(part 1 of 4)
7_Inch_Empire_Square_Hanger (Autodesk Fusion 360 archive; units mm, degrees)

design "7 Inch Empire Square Hanger" references "Speed Square_7IN_F360 v2"
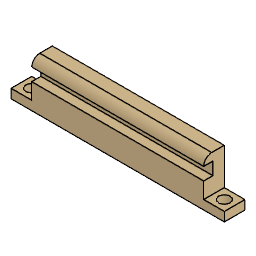
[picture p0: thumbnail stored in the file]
sketch "Square Hanger" plane through (0, 0, 0) normal (0, 0, 1) x axis (1, 0, 0)
  line L1 (75, 0) -> (0, 0)
  line L2 (75, 9) -> (75, 0)
  line L3 (0, 9) -> (75, 9)
  line L4 (0, 0) -> (0, 9)
  line L5 (-9, 0) -> (0, 0)
  line L6 (-9, 9) -> (-9, 0)
  line L7 (0, 9) -> (-9, 9)
  line L8 (0, 0) -> (0, 9)
  line L9 (84, 9) -> (75, 9)
  line L10 (84, 0) -> (84, 9)
  line L11 (75, 0) -> (84, 0)
  line L12 (75, 9) -> (75, 0)
  line L13 (79.5, 0) -> (79.5, 9)
  line L14 (84, 4.5) -> (75, 4.5)
  line L15 (0, 4.5) -> (-9, 4.5)
  line L16 (-4.5, 0) -> (-4.5, 9)
  circle C1 centre (79.5, 4.5) radius 2.5
  circle C2 centre (-4.5, 4.5) radius 2.5
  point P1 (0, 0)
  point P2 (0, 0)
  point P12 (79.5, 9)
  point P13 (79.5, 0)
  point P14 (75, 4.5)
  point P15 (84, 4.5)
  point P16 (-9, 4.5)
  point P17 (0, 4.5)
  point P18 (-4.5, 9)
  point P19 (-4.5, 0)
  point P20 (79.5, 4.5)
  point P21 (-4.5, 4.5)
  point P3 (75, 0)
  point P5 (0, 9)
  point P6 (-9, 0)
  point P8 (0, 9)
  point P4 (75, 9)
  point P9 (84, 9)
  point P11 (75, 0)
  horizontal L1
  vertical L2
  horizontal L3
  vertical L4
  coincident P1 P2
  horizontal L5
  vertical L6
  horizontal L7
  vertical L8
  horizontal L9
  vertical L10
  horizontal L11
  vertical L12
  midpoint L9 P12
  midpoint L11 P13
  midpoint L12 P14
  midpoint L10 P15
  midpoint L6 P16
  midpoint L8 P17
  midpoint L7 P18
  midpoint L5 P19
  midpoint L14 P20
  midpoint L15 P21
  dimension "d1" distance P2 P3 = 75
  dimension "d2" distance P2 P5 = 9
  dimension "d3" distance P2 P6 = 9 (= "d2")
  dimension "d4" distance P2 P8 = 9 (= "d2")
  dimension "d5" distance P4 P9 = 9 (= "d2")
  dimension "d6" distance P4 P11 = 9 (= "d2")
  dimension "d7" diameter C1 = 5
  dimension "d8" diameter C2 = 5
extrude "Extrude1" new body sketch "Square Hanger" profile of L1 L2 L3 L4 L8 L12 along normal blind 20 bodies "Square Hanger"
extrude "Extrude2" add sketch "Square Hanger" profile of L2 L4 L5 L6 L7 L8 L9 L10 L11 L12 C1 C2 along normal blind 4
sketch "Sketch2" plane through (0, 0, 0) normal (0, -1, 0) x axis (1, 0, 0)
  line L1 (84, 0) -> (-9, 0)
  line L2 (84, 4) -> (84, 0)
  line L3 (75, 4) -> (84, 4)
  line L4 (75, 20) -> (75, 4)
  line L5 (0, 20) -> (75, 20)
  line L6 (0, 4) -> (0, 20)
  line L7 (-9, 4) -> (0, 4)
  line L8 (-9, 0) -> (-9, 4)
  line L9 (0, 16.5) -> (75, 16.5)
  line L10 (0, 11) -> (0, 16.5)
  line L11 (75, 11) -> (0, 11)
  line L12 (75, 16.5) -> (75, 11)
  line L13 (75, 0) -> (0, 0)
  point P10 (75, 16.5)
  point P13 (75, 11)
  horizontal L9
  vertical L10
  horizontal L11
  vertical L12
  coincident L4 P10
  dimension "d13" distance P10 P13 = 5.5
  dimension "d14" distance L11 L13 = 11
extrude "Extrude3" cut sketch "Sketch2" profile of L4 L6 L9 L10 L11 L12 against normal blind 4
fillet "Fillet1" radius 3.5
component_insert "Component Insert"
named bodies: "Square Hanger"

design "Speed Square_7IN_F360 v2"
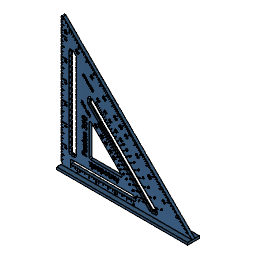
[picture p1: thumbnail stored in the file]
parameter "Etch_Diameter" = 0.635
parameter "Scale_Rule_Span" = 25.4
parameter "Scale_Triangle" = 177.8
parameter "Scale_Notch_Span" = 6.35
parameter "Square_Thickness" = 3.81
parameter "Square_Fense_Thickness" = 15.875
parameter "Scale_Rule_Depth" = 0.254
parameter "d473" = 3.175
sketch "MasterShape" plane through (0, 0, 0) normal (0, 1, 0) x axis (1, 0, 0)
  line L1 (177.8, 1.5875) -> (0, 1.5875)
  line L2 (0, -176.2125) -> (177.8, 1.5875)
  line L3 (0, 1.5875) -> (0, -176.2125)
  line L4 (177.8, 1.5875) -> (0, 1.5875)
  line L5 (177.8, 4.7625) -> (177.8, 1.5875)
  line L6 (0, 4.7625) -> (177.8, 4.7625)
  line L7 (0, 1.5875) -> (0, 4.7625)
  line L8 (19.05, -17.4625) -> (12.7, -17.4625)
  line L9 (19.05, -134.7119) -> (19.05, -17.4625)
  line L10 (12.7, -141.0619) -> (19.05, -134.7119)
  line L11 (12.7, -17.4625) -> (12.7, -141.0619)
  line L12 (104.0981, -4.7625) -> (12.7, -4.7625)
  line L13 (38.1, -70.7606) -> (104.0981, -4.7625)
  line L14 (38.1, -23.8125) -> (38.1, -70.7606)
  line L15 (38.1, -97.7013) -> (38.1, -88.7211)
  line L16 (131.0388, -4.7625) -> (38.1, -97.7013)
  line L17 (122.0586, -4.7625) -> (131.0388, -4.7625)
  line L18 (38.1, -88.7211) -> (122.0586, -4.7625)
  line L19 (38.1, -88.7211) -> (38.1, -70.7606)
  line L20 (85.0481, -23.8125) -> (38.1, -23.8125)
  line L21 (122.0586, -4.7625) -> (104.0981, -4.7625)
  line L22 (85.0481, -23.8125) -> (38.1, -70.7606)
  line L23 (12.7, -4.7625) -> (12.7, -17.4625)
  line L24 (12.7, -11.1125) -> (12.7, -4.7625)
  line L25 (97.7481, -11.1125) -> (12.7, -11.1125)
  line L26 (104.0981, -4.7625) -> (97.7481, -11.1125)
  arc A1 centre (0, 0) radius 1.5875 clockwise from (0, 1.5875) to (0, -1.5875)
  point P1 (0, 0)
  point P2 (0, 0)
  point P20 (0, -1.5875)
  point P21 (85.0481, -23.8125)
  point P22 (12.7, -11.1125)
  point P23 (97.7481, -11.1125)
  point P5 (0, -176.2125)
  point P3 (0, 1.5875)
  point P7 (0, 4.7625)
  point P12 (12.7, -4.7625)
  coincident P1 P2
  tangent L1 A1
  horizontal L1
  perpendicular L1 L3
  horizontal L4
  vertical L5
  horizontal L6
  vertical L7
  vertical L9
  vertical L11
  parallel L2 L10
  horizontal L12
  parallel L2 L13
  parallel L9 L15
  parallel L2 L16
  parallel L14 L19
  horizontal L17
  parallel L16 L18
  coincident L3 P20
  coincident L13 P21
  perpendicular L14 L20
  collinear L12 L17
  horizontal L8
  vertical L23
  coincident L23 P22
  perpendicular L12 L24
  coincident L13 P23
  perpendicular L23 L25
  dimension "d1" diameter A1 = 3.175
  dimension "d2" distance L1 P5 = 177.8 (= "Scale_Triangle")
  dimension "d3" angle L1 L2 = 45
  dimension "d4" distance P3 P7 = 3.175
  dimension "d5" distance L3 L11 = 12.7
  dimension "d6" distance L2 L10 = 15.875
  dimension "d7" distance L9 L11 = 6.35
  dimension "d8" distance L9 L14 = 19.05
  dimension "d12" distance L2 L13 = 47.625
  dimension "d13" distance L1 L17 = 6.35
  dimension "d15" distance L2 L18 = 34.925
  dimension "d16" distance L16 L18 = 6.35
  dimension "d72" distance L1 L8 = 19.05
  dimension "d73" distance L1 L20 = 25.4
  dimension "d74" distance P12 P22 = 6.35
  dimension "d564" distance P7 = 0.635
sketch "Inch_Scale" plane through (0, 0, 0) normal (0, 1, 0) x axis (1, 0, 0)
  line L1 (0, 1.5875) -> (0, -176.2125)
  line L2 (177.8, 1.5875) -> (0, 1.5875)
  line L3 (0, -176.2125) -> (177.8, 1.5875)
  line L4 (12.7, -17.4625) -> (12.7, -141.0619)
  line L5 (19.05, -134.7119) -> (19.05, -17.4625)
  line L6 (19.05, -17.4625) -> (12.7, -17.4625)
  line L7 (12.7, -141.0619) -> (19.05, -134.7119)
  line L8 (131.0388, -4.7625) -> (38.1, -97.7013)
  line L9 (38.1, -97.7013) -> (38.1, -88.7211)
  line L10 (38.1, -88.7211) -> (122.0586, -4.7625)
  line L11 (122.0586, -4.7625) -> (131.0388, -4.7625)
  line L12 (104.0981, -4.7625) -> (12.7, -4.7625)
  line L13 (38.1, -23.8125) -> (38.1, -70.7606)
  line L14 (38.1, -70.7606) -> (104.0981, -4.7625)
  line L15 (7.62, -24.13) -> (0, -24.13)
  line L16 (0, -20.32) -> (1.27, -20.32)
  line L17 (0, -23.495) -> (7.62, -23.495)
  line L18 (0, -17.145) -> (2.54, -17.145)
  line L19 (0, -17.4625) -> (2.54, -17.4625)
  line L20 (0, -1.27) -> (1.27, -1.27)
  line L21 (2.54, -5.08) -> (0, -5.08)
  line L22 (2.54, -17.78) -> (0, -17.78)
  line L23 (0, -1.5875) -> (1.27, -1.5875)
  line L24 (0, -23.8125) -> (7.62, -23.8125)
  line L25 (0, -11.1125) -> (3.81, -11.1125)
  line L26 (1.27, -20.955) -> (0, -20.955)
  line L27 (3.81, -11.43) -> (0, -11.43)
  line L28 (0, -14.2875) -> (1.27, -14.2875)
  line L29 (0, -10.795) -> (3.81, -10.795)
  line L30 (0, -4.445) -> (2.54, -4.445)
  line L31 (0, -4.7625) -> (2.54, -4.7625)
  line L32 (1.27, -8.255) -> (0, -8.255)
  line L33 (0, -13.97) -> (1.27, -13.97)
  line L34 (0, -7.9375) -> (1.27, -7.9375)
  line L35 (0, -7.62) -> (1.27, -7.62)
  line L36 (1.27, -1.905) -> (0, -1.905)
  line L37 (1.27, -14.605) -> (0, -14.605)
  line L38 (0, -20.6375) -> (1.27, -20.6375)
  line L39 (15.5575, -4.7625) -> (15.5575, -3.4925)
  line L40 (16.1925, -3.4925) -> (16.1925, -4.7625)
  line L41 (15.875, -4.7625) -> (15.875, -3.4925)
  line L42 (12.3825, -4.7625) -> (12.3825, -0.9525)
  line L43 (13.0175, -0.9525) -> (13.0175, -4.7625)
  line L44 (12.7, -4.7625) -> (12.7, -0.9525)
  line L45 (18.7325, -4.7625) -> (18.7325, -2.2225)
  line L46 (19.3675, -2.2225) -> (19.3675, -4.7625)
  line L47 (19.05, -4.7625) -> (19.05, -2.2225)
  line L48 (21.9075, -4.7625) -> (21.9075, -3.4925)
  line L49 (22.5425, -3.4925) -> (22.5425, -4.7625)
  line L50 (22.225, -4.7625) -> (22.225, -3.4925)
  line L51 (12.7, -23.8125) -> (7.62, -23.8125)
  line L52 (12.954, -25.059) -> (10.795, -23.8125)
  line L53 (12.954, -22.566) -> (12.954, -25.059)
  line L54 (10.795, -23.8125) -> (12.954, -22.566)
  line L55 (12.954, -23.8125) -> (12.7, -23.8125)
  line L56 (19.05, -20.6375) -> (1.27, -20.6375)
  line L57 (20.955, -20.6375) -> (19.05, -20.6375)
  line L58 (18.796, -21.884) -> (20.955, -20.6375)
  line L59 (18.796, -19.391) -> (18.796, -21.884)
  line L60 (20.955, -20.6375) -> (18.796, -19.391)
  arc A1 centre (1.27, -1.5875) radius 0.3175 clockwise from (1.27, -1.27) to (1.27, -1.905)
  arc A2 centre (1.27, -7.9375) radius 0.3175 clockwise from (1.27, -7.62) to (1.27, -8.255)
  arc A3 centre (2.54, -4.7625) radius 0.3175 clockwise from (2.54, -4.445) to (2.54, -5.08)
  arc A4 centre (1.27, -20.6375) radius 0.3175 clockwise from (1.27, -20.32) to (1.27, -20.955)
  arc A5 centre (0, -1.5875) radius 0.3175 clockwise from (0, -1.905) to (0, -1.27)
  arc A6 centre (0, -20.6375) radius 0.3175 clockwise from (0, -20.955) to (0, -20.32)
  arc A7 centre (0, -11.1125) radius 0.3175 clockwise from (0, -11.43) to (0, -10.795)
  arc A8 centre (0, -17.4625) radius 0.3175 clockwise from (0, -17.78) to (0, -17.145)
  arc A9 centre (0, -23.8125) radius 0.3175 clockwise from (0, -24.13) to (0, -23.495)
  arc A10 centre (0, -7.9375) radius 0.3175 clockwise from (0, -8.255) to (0, -7.62)
  arc A11 centre (2.54, -17.4625) radius 0.3175 clockwise from (2.54, -17.145) to (2.54, -17.78)
  arc A12 centre (7.62, -23.8125) radius 0.3175 clockwise from (7.62, -23.495) to (7.62, -24.13)
  arc A13 centre (1.27, -14.2875) radius 0.3175 clockwise from (1.27, -13.97) to (1.27, -14.605)
  arc A14 centre (0, -4.7625) radius 0.3175 clockwise from (0, -5.08) to (0, -4.445)
  arc A15 centre (0, -14.2875) radius 0.3175 clockwise from (0, -14.605) to (0, -13.97)
  arc A16 centre (3.81, -11.1125) radius 0.3175 clockwise from (3.81, -10.795) to (3.81, -11.43)
  arc A17 centre (15.875, -4.7625) radius 0.3175 clockwise from (16.1925, -4.7625) to (15.5575, -4.7625)
  arc A18 centre (15.875, -3.4925) radius 0.3175 clockwise from (15.5575, -3.4925) to (16.1925, -3.4925)
  arc A19 centre (12.7, -4.7625) radius 0.3175 clockwise from (13.0175, -4.7625) to (12.3825, -4.7625)
  arc A20 centre (12.7, -0.9525) radius 0.3175 clockwise from (12.3825, -0.9525) to (13.0175, -0.9525)
  arc A21 centre (19.05, -4.7625) radius 0.3175 clockwise from (19.3675, -4.7625) to (18.7325, -4.7625)
  arc A22 centre (19.05, -2.2225) radius 0.3175 clockwise from (18.7325, -2.2225) to (19.3675, -2.2225)
  arc A23 centre (22.225, -4.7625) radius 0.3175 clockwise from (22.5425, -4.7625) to (21.9075, -4.7625)
  arc A24 centre (22.225, -3.4925) radius 0.3175 clockwise from (21.9075, -3.4925) to (22.5425, -3.4925)
  point P1 (0, 0)
  point P35 (0, 0)
  point P73 (0, -1.5875)
  point P74 (0, -1.5875)
  point P32 (0, -4.7625)
  point P42 (0, -7.9375)
  point P44 (0, -11.1125)
  point P52 (0, -14.2875)
  point P79 (0, -17.4625)
  point P66 (0, -20.6375)
  point P46 (0, -23.8125)
  point P85 (15.875, -4.7625)
  point P24 (12.7, -4.7625)
  point P92 (12.7, -4.7625)
  point P98 (19.05, -4.7625)
  point P103 (22.225, -4.7625)
  point P54 (7.62, -23.8125)
  point P105 (7.62, -23.8125)
  point P106 (12.7, -23.8125)
  point P107 (10.795, -23.8125)
  point P110 (12.954, -23.8125)
  point P65 (1.27, -20.6375)
  point P111 (1.27, -20.6375)
  point P112 (19.05, -20.6375)
  point P116 (18.796, -20.6375)
  point P41 (3.81, -11.1125)
  point P31 (2.54, -4.7625)
  point P75 (2.54, -17.4625)
  point P40 (1.27, -7.9375)
  point P51 (1.27, -14.2875)
  point P64 (1.27, -1.5875)
  point P84 (15.875, -3.4925)
  point P86 (0, 0)
  point P91 (12.7, -0.9525)
  point P97 (19.05, -2.2225)
  point P100 (22.225, -3.4925)
  point P113 (20.955, -20.6375)
  tangent L17 A9
  tangent L15 A9
  parallel L15 L17
  tangent L15 A12
  tangent L17 A12
  tangent A7 L29
  tangent A7 L27
  parallel L27 L29
  tangent L27 A16
  tangent L29 A16
  tangent A14 L30
  tangent L21 A14
  parallel L21 L30
  tangent A3 L21
  tangent A3 L30
  tangent L18 A8
  tangent A8 L22
  parallel L18 L22
  tangent L22 A11
  tangent L18 A11
  horizontal L19
  tangent A10 L35
  tangent A10 L32
  parallel L32 L35
  tangent A2 L32
  tangent A2 L35
  tangent A15 L33
  tangent A15 L37
  parallel L33 L37
  tangent A13 L37
  tangent A13 L33
  tangent L16 A6
  tangent A6 L26
  parallel L16 L26
  tangent A4 L26
  tangent L16 A4
  tangent A5 L20
  tangent A5 L36
  parallel L20 L36
  tangent A1 L36
  tangent A1 L20
  coincident P1 P35
  coincident P73 P74
  coincident L1 P74
  coincident L1 P32
  coincident L1 P42
  coincident L1 P44
  coincident L1 P52
  coincident L1 P79
  coincident L1 P66
  coincident L1 P46
  tangent L39 A17
  tangent A17 L40
  parallel L39 L40
  tangent L40 A18
  tangent L39 A18
  coincident L12 P85
  perpendicular L12 L41
  tangent L42 A19
  tangent A19 L43
  parallel L42 L43
  tangent L43 A20
  tangent L42 A20
  coincident P24 P92
  perpendicular L12 L44
  tangent L45 A21
  tangent A21 L46
  parallel L45 L46
  tangent L46 A22
  tangent L45 A22
  coincident L12 P98
  perpendicular L12 L47
  tangent L48 A23
  tangent A23 L49
  parallel L48 L49
  tangent L49 A24
  tangent L48 A24
  coincident L12 P103
  vertical L50
  coincident P54 P105
  coincident L4 P106
  horizontal L51
  coincident L51 P107
  perpendicular L51 L53
  midpoint L53 P110
  horizontal L55
  coincident P65 P111
  coincident L5 P112
  horizontal L56
  perpendicular L5 L57
  perpendicular L56 L59
  midpoint L59 P116
  coincident L56 P116
  dimension "d46" diameter A9 = 0.635
  dimension "d47" distance P46 P54 = 7.62
  dimension "d48" diameter A7 = 0.635 (= "d60")
  dimension "d49" distance P41 P44 = 3.81
  dimension "d50" diameter A14 = 0.635 (= "d60")
  dimension "d51" distance P31 P32 = 2.54
  dimension "d52" diameter A8 = 0.635
  dimension "d53" distance P75 P79 = 2.54
  dimension "d54" diameter A10 = 0.635 (= "d60")
  dimension "d55" distance P40 P42 = 1.27
  dimension "d56" diameter A15 = 0.635
  dimension "d57" distance P51 P52 = 1.27
  dimension "d58" diameter A6 = 0.635
  dimension "d59" distance P65 P66 = 1.27
  dimension "d60" diameter A5 = 0.635
  dimension "d61" distance P64 P73 = 1.27
  dimension "d63" distance L2 L23 = 3.175 (= "0.125 in * ( Scale )")
  dimension "d64" distance L2 L31 = 6.35 (= "0.25 in * ( Scale )")
  dimension "d65" distance L2 L34 = 9.525 (= "0.375 in * ( Scale )")
  dimension "d66" distance L2 L25 = 12.7 (= "0.50 in * ( Scale )")
  dimension "d67" distance L2 L28 = 15.875 (= "0.625 in * ( Scale )")
  dimension "d68" distance L2 L19 = 19.05 (= "0.75 in * ( Scale )")
  dimension "d69" distance L2 L38 = 22.225 (= "0.875 in * ( Scale )")
  dimension "d70" distance L2 L24 = 25.4 (= "1.00 in * ( Scale )")
  dimension "d80" diameter A17 = 0.635 (= "d60")
  dimension "d81" distance P84 P85 = 1.27
  dimension "d82" distance L41 P86 = 15.875
  dimension "d83" diameter A19 = 0.635
  dimension "d84" distance P91 P92 = 3.81
  dimension "d85" diameter A21 = 0.635
  dimension "d86" distance P97 P98 = 2.54
  dimension "d87" distance L1 L47 = 19.05
  dimension "d88" diameter A23 = 0.635 (= "d60")
  dimension "d89" distance P100 P103 = 1.27
  dimension "d90" distance P86 L50 = 22.225
  dimension "d95" distance L4 L53 = 0.254
  dimension "d96" angle L52 L54 = 60
  dimension "d97" distance P106 P107 = 1.905
  dimension "d101" distance L5 L59 = 0.254 (= "d95")
  dimension "d102" distance P112 P113 = 1.905 (= "d97")
  dimension "d103" angle L58 L60 = 60 (= "d96")
sketch "Front_Scale_Text" plane through (0, 0, 0) normal (0, 1, 0) x axis (1, 0, 0)
  line L1 (7.9375, -20.6375) -> (4.7625, -20.6375)
  line L2 (7.9375, -19.05) -> (7.9375, -22.225)
  line L3 (7.9375, -46.0375) -> (4.7625, -46.0375)
  line L4 (7.9375, -44.3107) -> (7.9375, -47.7643)
  line L5 (7.9375, -69.85) -> (7.9375, -73.025)
  line L6 (7.9375, -71.4375) -> (4.7625, -71.4375)
  line L7 (7.9375, -122.2375) -> (4.7625, -122.2375)
  line L8 (7.9375, -96.8375) -> (4.7625, -96.8375)
  line L9 (7.9375, -120.65) -> (7.9375, -123.825)
  line L10 (7.9375, -95.25) -> (7.9375, -98.425)
  line L11 (7.9375, -147.6375) -> (0, -147.6375)
  line L12 (7.9375, -146.05) -> (7.9375, -149.225)
  line L13 (7.9375, -171.45) -> (7.9375, -174.625)
  line L14 (7.9375, -173.0375) -> (4.7625, -173.0375)
  line L15 (7.9375, -300.0375) -> (4.7625, -300.0375)
  line L16 (7.9375, -198.4375) -> (4.7625, -198.4375)
  line L17 (7.9375, -223.8375) -> (4.7625, -223.8375)
  line L18 (7.9375, -222.25) -> (7.9375, -225.425)
  line L19 (7.9375, -247.65) -> (7.9375, -250.825)
  line L20 (7.9375, -273.05) -> (7.9375, -276.225)
  line L21 (7.9375, -249.2375) -> (4.7625, -249.2375)
  line L22 (7.9375, -274.6375) -> (4.7625, -274.6375)
  line L23 (7.9375, -298.45) -> (7.9375, -301.625)
  line L24 (7.9375, -196.85) -> (7.9375, -200.025)
  line L25 (0, 1.5875) -> (0, -176.2125)
  line L26 (177.8, 1.5875) -> (0, 1.5875)
  line L27 (0, -176.2125) -> (177.8, 1.5875)
  line L28 (12.7, -17.4625) -> (12.7, -141.0619)
  line L29 (12.7, -141.0619) -> (19.05, -134.7119)
  line L30 (19.05, -134.7119) -> (19.05, -17.4625)
  line L31 (19.05, -17.4625) -> (12.7, -17.4625)
  line L32 (97.7481, -11.1125) -> (12.7, -11.1125)
  line L33 (12.7, -4.7625) -> (12.7, -17.4625)
  line L34 (104.0981, -4.7625) -> (12.7, -4.7625)
  line L35 (38.1, -70.7606) -> (104.0981, -4.7625)
  line L36 (85.0481, -23.8125) -> (38.1, -23.8125)
  line L37 (38.1, -23.8125) -> (38.1, -70.7606)
  line L38 (38.1, -88.7211) -> (122.0586, -4.7625)
  line L39 (131.0388, -4.7625) -> (38.1, -97.7013)
  line L40 (38.1, -97.7013) -> (38.1, -88.7211)
  line L41 (122.0586, -4.7625) -> (131.0388, -4.7625)
  line L42 (23.7727, 0.9525) -> (20.6773, 0.9525)
  line L43 (49.1727, 0.9525) -> (46.0773, 0.9525)
  line L44 (74.5727, 0.9525) -> (71.4773, 0.9525)
  line L45 (99.9727, 0.9525) -> (96.8773, 0.9525)
  line L46 (125.3727, 0.9525) -> (122.2773, 0.9525)
  line L47 (150.7727, 0.9525) -> (147.6773, 0.9525)
  line L48 (176.1727, 0.9525) -> (173.0773, 0.9525)
  line L49 (201.5727, 0.9525) -> (198.4773, 0.9525)
  line L50 (226.9727, 0.9525) -> (223.8773, 0.9525)
  line L51 (7.9375, -155.575) -> (7.9375, -158.75)
  line L52 (7.9375, -157.1625) -> (0, -157.1625)
  point P46 (7.9375, -20.6375)
  point P20 (7.9375, -46.0375)
  point P2 (7.9375, -71.4375)
  point P32 (7.9375, -96.8375)
  point P45 (7.9375, -122.2375)
  point P34 (7.9375, -147.6375)
  point P6 (7.9375, -173.0375)
  point P29 (7.9375, -198.4375)
  point P24 (7.9375, -223.8375)
  point P11 (7.9375, -249.2375)
  point P38 (7.9375, -274.6375)
  point P14 (7.9375, -300.0375)
  point P86 (22.225, 0.9525)
  point P89 (47.625, 0.9525)
  point P92 (73.025, 0.9525)
  point P95 (98.425, 0.9525)
  point P98 (123.825, 0.9525)
  point P101 (149.225, 0.9525)
  point P104 (174.625, 0.9525)
  point P107 (200.025, 0.9525)
  point P110 (225.425, 0.9525)
  point P35 (0, -147.6375)
  point P111 (7.9375, -157.1625)
  vertical L2
  midpoint P46 L2
  vertical L4
  midpoint P20 L4
  vertical L5
  midpoint P2 L5
  vertical L10
  midpoint P32 L10
  vertical L9
  midpoint P45 L9
  vertical L12
  midpoint P34 L12
  vertical L13
  midpoint P6 L13
  collinear L2 L4
  collinear L4 L5
  collinear L5 L10
  collinear L9 L10
  collinear L9 L12
  collinear L12 L13
  vertical L24
  midpoint P29 L24
  vertical L18
  midpoint P24 L18
  vertical L19
  midpoint P11 L19
  vertical L20
  midpoint P38 L20
  vertical L23
  midpoint P14 L23
  collinear L13 L24
  collinear L18 L24
  collinear L18 L20
  collinear L19 L23
  collinear L20 L23
  horizontal L42
  midpoint L42 P86
  horizontal L43
  midpoint P89 L43
  horizontal L44
  midpoint P92 L44
  horizontal L45
  midpoint P95 L45
  horizontal L46
  midpoint P98 L46
  horizontal L47
  midpoint P101 L47
  horizontal L48
  midpoint P104 L48
  horizontal L49
  midpoint P107 L49
  horizontal L50
  midpoint P110 L50
  collinear L42 L43
  collinear L43 L44
  collinear L44 L45
  collinear L45 L46
  collinear L46 L47
  collinear L47 L48
  collinear L48 L49
  collinear L49 L50
  coincident P35 L25
  vertical L51
  midpoint P111 L51
  dimension "d429" distance L3 L6 = 25.4 (= "Scale_Rule_Span")
  dimension "d430" distance L6 L8 = 25.4 (= "Scale_Rule_Span")
  dimension "d431" distance L7 L8 = 25.4 (= "Scale_Rule_Span")
  dimension "d432" distance L7 L11 = 25.4 (= "Scale_Rule_Span")
  dimension "d433" distance L11 L14 = 25.4 (= "Scale_Rule_Span")
  dimension "d444" distance L14 L16 = 25.4 (= "Scale_Rule_Span")
  dimension "d445" distance L16 L17 = 25.4 (= "Scale_Rule_Span")
  dimension "d446" distance L17 L21 = 25.4 (= "Scale_Rule_Span")
  dimension "d447" distance L21 L22 = 25.4 (= "Scale_Rule_Span")
  dimension "d448" distance L15 L22 = 25.4 (= "Scale_Rule_Span")
  dimension "d449" distance L1 L26 = 22.225
  dimension "d450" distance L1 L3 = 25.4 (= "Scale_Rule_Span")
  dimension "d451" distance L2 L25 = 7.9375
  dimension "d503" distance L25 P86 = 22.225
  dimension "d505" distance L26 L42 = 0.635
  dimension "d1049" distance L11 L52 = 9.525 (= "Scale_Rule_Span * 0.375")
  dimension "d403" Text1-Height = 3.175
  dimension "d404" Text2-Height = 3.175
  dimension "d405" Text3-Height = 3.175
  dimension "d406" Text4-Height = 3.175
  dimension "d407" Text5-Height = 3.175
  dimension "d408" Text6-Height = 3.175
  dimension "d409" Text7-Height = 3.175
  dimension "d410" Text8-Height = 3.175
  dimension "d411" Text9-Height = 3.175
  dimension "d412" Text10-Height = 3.175
  dimension "d413" Text11-Height = 3.175
  dimension "d414" Text12-Height = 3.175
  dimension "d504" Text13-Height = 3.175
  dimension "d506" Text14-Height = 3.175
  dimension "d507" Text15-Height = 3.175
  dimension "d508" Text16-Height = 3.175
  dimension "d509" Text17-Height = 3.175
  dimension "d510" Text18-Height = 3.175
  dimension "d511" Text19-Height = 3.175
  dimension "d512" Text20-Height = 3.175
  dimension "d513" Text21-Height = 3.175
  dimension "d1048" Text22-Height = 3.175
sketch "Back_Scale_Text" plane through (0, 0, 0) normal (0, 1, 0) x axis (1, 0, 0)
  line L1 (4.7625, -149.225) -> (4.7625, -146.05)
  line L2 (4.7625, -98.425) -> (4.7625, -95.25)
  line L3 (7.9375, -200.025) -> (4.7625, -200.025)
  line L4 (7.9375, -222.25) -> (7.9375, -225.425)
  line L5 (7.9375, -73.025) -> (4.7625, -73.025)
  line L6 (4.7625, -225.425) -> (4.7625, -222.25)
  line L7 (4.7625, -95.25) -> (7.9375, -95.25)
  line L8 (4.7625, -19.05) -> (7.9375, -19.05)
  line L9 (7.9375, -225.425) -> (4.7625, -225.425)
  line L10 (7.9375, -46.0375) -> (4.7625, -46.0375)
  line L11 (4.7625, -47.625) -> (4.7625, -44.45)
  line L12 (7.9375, -47.625) -> (4.7625, -47.625)
  line L13 (4.7625, -146.05) -> (7.9375, -146.05)
  line L14 (7.9375, -149.225) -> (4.7625, -149.225)
  line L15 (4.7625, -200.025) -> (4.7625, -196.85)
  line L16 (4.7625, -44.45) -> (7.9375, -44.45)
  line L17 (4.7625, -120.65) -> (7.9375, -120.65)
  line L18 (7.9375, -96.8375) -> (4.7625, -96.8375)
  line L19 (7.9375, -98.425) -> (4.7625, -98.425)
  line L20 (4.7625, -250.825) -> (4.7625, -247.65)
  line L21 (7.9375, -249.2375) -> (4.7625, -249.2375)
  line L22 (7.9375, -276.225) -> (4.7625, -276.225)
  line L23 (7.9375, -147.6375) -> (4.7625, -147.6375)
  line L24 (7.9375, -250.825) -> (4.7625, -250.825)
  line L25 (4.7625, -247.65) -> (7.9375, -247.65)
  line L26 (4.7625, -276.225) -> (4.7625, -273.05)
  line L27 (4.7625, -298.45) -> (7.9375, -298.45)
  line L28 (7.9375, -274.6375) -> (4.7625, -274.6375)
  line L29 (7.9375, -301.625) -> (4.7625, -301.625)
  line L30 (4.7625, -301.625) -> (4.7625, -298.45)
  line L31 (7.9375, -300.0375) -> (4.7625, -300.0375)
  line L32 (4.7625, -273.05) -> (7.9375, -273.05)
  line L33 (7.9375, -22.225) -> (4.7625, -22.225)
  line L34 (4.7625, -123.825) -> (4.7625, -120.65)
  line L35 (7.9375, -223.8375) -> (4.7625, -223.8375)
  line L36 (7.9375, -122.2375) -> (4.7625, -122.2375)
  line L37 (7.9375, -20.6375) -> (4.7625, -20.6375)
  line L38 (4.7625, -69.85) -> (7.9375, -69.85)
  line L39 (7.9375, -71.4375) -> (4.7625, -71.4375)
  line L40 (4.7625, -22.225) -> (4.7625, -19.05)
  line L41 (7.9375, -123.825) -> (4.7625, -123.825)
  line L42 (4.7625, -222.25) -> (7.9375, -222.25)
  line L43 (4.7625, -73.025) -> (4.7625, -69.85)
  line L44 (7.9375, -44.45) -> (7.9375, -47.625)
  line L45 (4.7625, -174.625) -> (4.7625, -171.45)
  line L46 (7.9375, -174.625) -> (4.7625, -174.625)
  line L47 (4.7625, -196.85) -> (7.9375, -196.85)
  line L48 (7.9375, -198.4375) -> (4.7625, -198.4375)
  line L49 (7.9375, -171.45) -> (7.9375, -174.625)
  line L50 (7.9375, -19.05) -> (7.9375, -22.225)
  line L51 (7.9375, -95.25) -> (7.9375, -98.425)
  line L52 (7.9375, -69.85) -> (7.9375, -73.025)
  line L53 (7.9375, -273.05) -> (7.9375, -276.225)
  line L54 (7.9375, -196.85) -> (7.9375, -200.025)
  line L55 (7.9375, -120.65) -> (7.9375, -123.825)
  line L56 (7.9375, -146.05) -> (7.9375, -149.225)
  line L57 (7.9375, -173.0375) -> (4.7625, -173.0375)
  line L58 (7.9375, -298.45) -> (7.9375, -301.625)
  line L59 (7.9375, -247.65) -> (7.9375, -250.825)
  line L60 (4.7625, -171.45) -> (7.9375, -171.45)
  line L61 (0, 1.5875) -> (0, -176.2125)
  line L62 (177.8, 1.5875) -> (0, 1.5875)
  line L63 (0, -176.2125) -> (177.8, 1.5875)
  line L64 (19.05, -134.7119) -> (19.05, -17.4625)
  line L65 (12.7, -141.0619) -> (19.05, -134.7119)
  line L66 (12.7, -17.4625) -> (12.7, -141.0619)
  line L67 (19.05, -17.4625) -> (12.7, -17.4625)
  line L68 (97.7481, -11.1125) -> (12.7, -11.1125)
  line L69 (104.0981, -4.7625) -> (12.7, -4.7625)
  line L70 (12.7, -4.7625) -> (12.7, -17.4625)
  line L71 (38.1, -70.7606) -> (104.0981, -4.7625)
  line L72 (85.0481, -23.8125) -> (38.1, -23.8125)
  line L73 (38.1, -23.8125) -> (38.1, -70.7606)
  line L74 (38.1, -88.7211) -> (122.0586, -4.7625)
  line L75 (38.1, -97.7013) -> (38.1, -88.7211)
  line L76 (131.0388, -4.7625) -> (38.1, -97.7013)
  line L77 (122.0586, -4.7625) -> (131.0388, -4.7625)
  line L78 (24.1061, 0.9525) -> (20.3439, 0.9525)
  line L79 (49.5061, 0.9525) -> (45.7439, 0.9525)
  line L80 (74.9061, 0.9525) -> (71.1439, 0.9525)
  line L81 (100.3061, 0.9525) -> (96.5439, 0.9525)
  line L82 (125.7061, 0.9525) -> (121.9439, 0.9525)
  line L83 (151.1061, 0.9525) -> (147.3439, 0.9525)
  line L84 (176.5061, 0.9525) -> (172.7439, 0.9525)
  line L85 (201.9061, 0.9525) -> (198.1439, 0.9525)
  line L86 (227.3061, 0.9525) -> (223.5439, 0.9525)
  line L87 (7.9375, -157.1625) -> (0, -157.1625)
  line L88 (7.9375, -155.575) -> (7.9375, -158.75)
  point P3 (4.7625, -20.6375)
  point P8 (7.9375, -20.6375)
  point P61 (4.7625, -46.0375)
  point P56 (7.9375, -46.0375)
  point P29 (4.7625, -71.4375)
  point P27 (7.9375, -71.4375)
  point P64 (4.7625, -96.8375)
  point P54 (7.9375, -96.8375)
  point P12 (4.7625, -122.2375)
  point P5 (7.9375, -122.2375)
  point P66 (4.7625, -147.6375)
  point P69 (7.9375, -147.6375)
  point P24 (4.7625, -173.0375)
  point P36 (7.9375, -173.0375)
  point P55 (4.7625, -198.4375)
  point P51 (7.9375, -198.4375)
  point P62 (4.7625, -223.8375)
  point P60 (7.9375, -223.8375)
  point P22 (4.7625, -249.2375)
  point P38 (7.9375, -249.2375)
  point P19 (4.7625, -274.6375)
  point P20 (7.9375, -274.6375)
  point P43 (4.7625, -300.0375)
  point P33 (7.9375, -300.0375)
  point P112 (22.225, 0.9525)
  point P113 (47.625, 0.9525)
  point P116 (73.025, 0.9525)
  point P119 (98.425, 0.9525)
  point P122 (123.825, 0.9525)
  point P125 (149.225, 0.9525)
  point P128 (174.625, 0.9525)
  point P131 (200.025, 0.9525)
  point P134 (225.425, 0.9525)
  point P139 (7.9375, -157.1625)
  point P7 (7.9375, -19.05)
  point P9 (4.7625, -19.05)
  point P4 (7.9375, -22.225)
  point P45 (7.9375, -44.45)
  point P58 (4.7625, -44.45)
  point P46 (7.9375, -47.625)
  point P26 (4.7625, -69.85)
  point P28 (7.9375, -69.85)
  point P35 (7.9375, -73.025)
  point P49 (4.7625, -95.25)
  point P53 (7.9375, -95.25)
  point P63 (7.9375, -98.425)
  point P16 (4.7625, -120.65)
  point P17 (7.9375, -120.65)
  point P11 (7.9375, -123.825)
  point P10 (7.9375, -146.05)
  point P65 (4.7625, -146.05)
  point P70 (7.9375, -149.225)
  point P31 (7.9375, -171.45)
  point P34 (4.7625, -171.45)
  point P37 (7.9375, -174.625)
  point P57 (7.9375, -196.85)
  point P71 (4.7625, -196.85)
  point P50 (7.9375, -200.025)
  point P52 (7.9375, -222.25)
  point P59 (4.7625, -222.25)
  point P72 (7.9375, -225.425)
  point P23 (7.9375, -247.65)
  point P32 (4.7625, -247.65)
  point P39 (7.9375, -250.825)
  point P14 (4.7625, -273.05)
  point P15 (7.9375, -273.05)
  point P13 (7.9375, -276.225)
  point P25 (7.9375, -298.45)
  point P42 (4.7625, -298.45)
  point P41 (7.9375, -301.625)
  horizontal L33
  vertical L50
  horizontal L8
  vertical L40
  midpoint P3 L40
  midpoint P8 L50
  horizontal L12
  vertical L44
  horizontal L16
  vertical L11
  midpoint P61 L11
  midpoint P56 L44
  horizontal L5
  vertical L52
  horizontal L38
  vertical L43
  midpoint P29 L43
  midpoint P27 L52
  horizontal L19
  vertical L51
  horizontal L7
  vertical L2
  midpoint P64 L2
  midpoint P54 L51
  horizontal L41
  vertical L55
  horizontal L17
  vertical L34
  midpoint P12 L34
  midpoint P5 L55
  horizontal L14
  vertical L56
  horizontal L13
  vertical L1
  midpoint P66 L1
  midpoint P69 L56
  horizontal L46
  vertical L49
  horizontal L60
  vertical L45
  midpoint P24 L45
  midpoint P36 L49
  collinear L44 L50
  collinear L44 L52
  collinear L51 L52
  collinear L51 L55
  collinear L55 L56
  collinear L49 L56
  horizontal L3
  vertical L54
  horizontal L47
  vertical L15
  midpoint P55 L15
  midpoint P51 L54
  horizontal L9
  vertical L4
  horizontal L42
  vertical L6
  midpoint P62 L6
  midpoint P60 L4
  horizontal L24
  vertical L59
  horizontal L25
  vertical L20
  midpoint P22 L20
  midpoint P38 L59
  horizontal L22
  vertical L53
  horizontal L32
  vertical L26
  midpoint P19 L26
  midpoint P20 L53
  horizontal L29
  vertical L58
  horizontal L27
  vertical L30
  midpoint P43 L30
  midpoint P33 L58
  collinear L49 L54
  collinear L4 L54
  collinear L4 L53
  collinear L58 L59
  collinear L53 L58
  parallel L69 L78
  midpoint L78 P112
  midpoint P113 L79
  midpoint P116 L80
  midpoint P119 L81
  midpoint P122 L82
  midpoint P125 L83
  midpoint P128 L84
  midpoint P131 L85
  midpoint P134 L86
  collinear L78 L79
  collinear L79 L80
  collinear L80 L81
  collinear L81 L82
  collinear L82 L83
  collinear L83 L84
  collinear L84 L85
  collinear L85 L86
  vertical L88
  midpoint P139 L88
  collinear L56 L88
  dimension "d464" distance P7 P9 = 3.175
  dimension "d465" distance P4 P7 = 3.175
  dimension "d466" distance P45 P58 = 3.175
  dimension "d467" distance P45 P46 = 3.175
  dimension "d468" distance P26 P28 = 3.175
  dimension "d469" distance P28 P35 = 3.175
  dimension "d470" distance P49 P53 = 3.175
  dimension "d471" distance P53 P63 = 3.175
  dimension "d472" distance P16 P17 = 3.175
  dimension "d473" distance P11 P17 = 3.175
  dimension "d474" distance P10 P65 = 3.175
  dimension "d475" distance P10 P70 = 3.175
  dimension "d476" distance P31 P34 = 3.175
  dimension "d477" distance P31 P37 = 3.175
  dimension "d478" distance L10 L39 = 25.4 (= "Scale_Rule_Span")
  dimension "d479" distance L18 L39 = 25.4 (= "Scale_Rule_Span")
  dimension "d480" distance L18 L36 = 25.4 (= "Scale_Rule_Span")
  dimension "d481" distance L23 L36 = 25.4 (= "Scale_Rule_Span")
  dimension "d482" distance L23 L57 = 25.4 (= "Scale_Rule_Span")
  dimension "d483" distance P57 P71 = 3.175
  dimension "d484" distance P50 P57 = 3.175
  dimension "d485" distance P52 P59 = 3.175
  dimension "d486" distance P52 P72 = 3.175
  dimension "d487" distance P23 P32 = 3.175
  dimension "d488" distance P23 P39 = 3.175
  dimension "d489" distance P14 P15 = 3.175
  dimension "d490" distance P13 P15 = 3.175
  dimension "d491" distance P25 P42 = 3.175
  dimension "d492" distance P25 P41 = 3.175
  dimension "d493" distance L48 L57 = 25.4 (= "Scale_Rule_Span")
  dimension "d494" distance L35 L48 = 25.4 (= "Scale_Rule_Span")
  dimension "d495" distance L21 L35 = 25.4 (= "Scale_Rule_Span")
  dimension "d496" distance L21 L28 = 25.4 (= "Scale_Rule_Span")
  dimension "d497" distance L28 L31 = 25.4 (= "Scale_Rule_Span")
  dimension "d498" distance L10 L37 = 25.4 (= "Scale_Rule_Span")
  dimension "d499" distance L37 L62 = 22.225
  dimension "d500" distance L50 L61 = 7.9375
  dimension "d518" distance L62 L78 = 0.635
  dimension "d519" distance L61 P112 = 22.225
  dimension "d528" distance P112 P113 = 25.4 (= "Scale_Rule_Span")
  dimension "d529" distance P113 P116 = 25.4 (= "Scale_Rule_Span")
  dimension "d530" distance P116 P119 = 25.4 (= "Scale_Rule_Span")
  dimension "d531" distance P119 P122 = 25.4 (= "Scale_Rule_Span")
  dimension "d532" distance P122 P125 = 25.4 (= "Scale_Rule_Span")
  dimension "d533" distance P125 P128 = 25.4 (= "Scale_Rule_Span")
  dimension "d534" distance P128 P131 = 25.4 (= "Scale_Rule_Span")
  dimension "d535" distance P131 P134 = 25.4 (= "Scale_Rule_Span")
  dimension "d1051" distance L23 L87 = 9.525 (= "Scale_Rule_Span * 0.375")
  dimension "d452" Text1-Height = 3.175
  dimension "d453" Text2-Height = 3.175
  dimension "d454" Text3-Height = 3.175
  dimension "d455" Text4-Height = 3.175
  dimension "d456" Text5-Height = 3.175
  dimension "d457" Text6-Height = 3.175
  dimension "d458" Text7-Height = 3.175
  dimension "d459" Text8-Height = 3.175
  dimension "d460" Text9-Height = 3.175
  dimension "d461" Text10-Height = 3.175
  dimension "d462" Text11-Height = 3.175
  dimension "d463" Text12-Height = 3.175
  dimension "d517" Text13-Height = 3.175
  dimension "d520" Text14-Height = 3.175
  dimension "d521" Text15-Height = 3.175
  dimension "d522" Text16-Height = 3.175
  dimension "d523" Text17-Height = 3.175
  dimension "d524" Text18-Height = 3.175
  dimension "d525" Text19-Height = 3.175
  dimension "d526" Text20-Height = 3.175
  dimension "d527" Text21-Height = 3.175
  dimension "d1050" Text22-Height = 3.175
